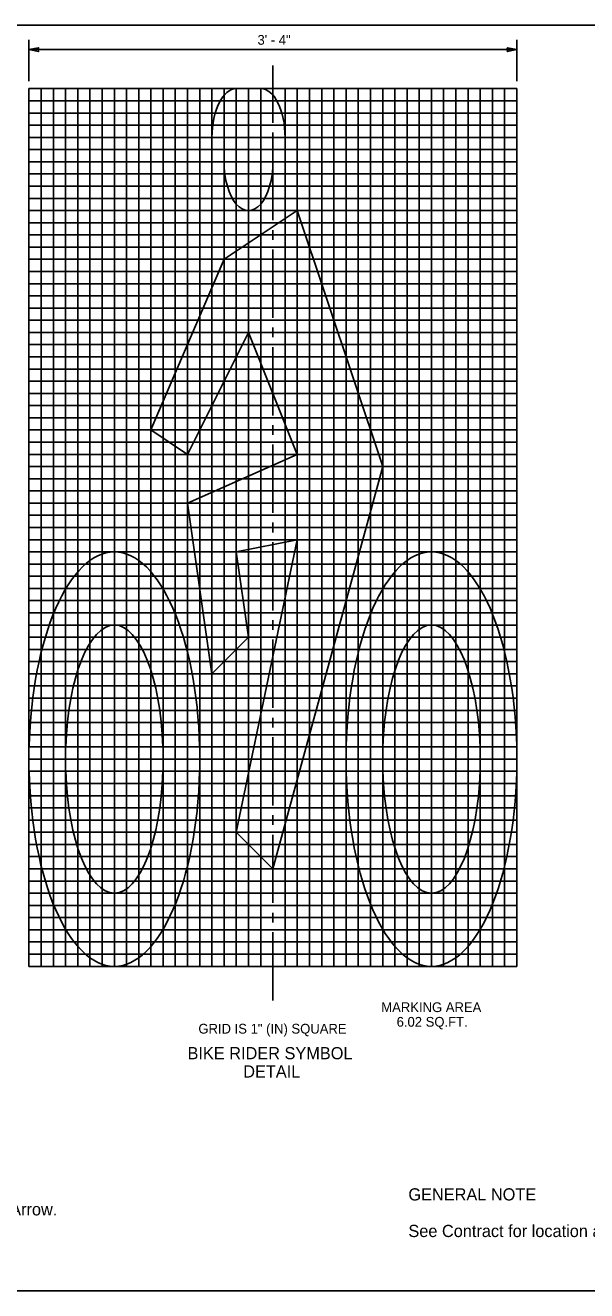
# Model space of a CAD drawing. Extents: x 99862 to 104211, y 98939 to 102076.
# Drawn here: x 101116 to 102036, y 100000 to 102076 of the extents above; entities that cross this region are included whole.
import ezdxf

# ---------------------------------------------------------------- set-up
doc = ezdxf.new("R2010")
doc.units = 0
for name, color, linetype in [('Level 1', 7, 'Continuous'), ('Level 15', 7, 'Continuous'), ('Level 2', 7, 'Continuous'), ('Level 20', 7, 'Continuous'), ('Level 7', 7, 'Continuous')]:
    doc.layers.add(name, color=color, linetype=linetype)

msp = doc.modelspace()

# ---------------------------------------------------------------- linework, layer by layer
at = {"layer": 'Level 1'}
msp.add_lwpolyline([(99862, 99999.5), (103151, 99999.5), (103151, 102075.5), (99862, 102075.5)], close=True, dxfattribs=at)
at = {"layer": 'Level 15'}
for p, q in [((101121.8, 101983.6), (101121.8, 102051.6)), ((101121.8, 102035.6), (101921.8, 102035.6)), ((101921.8, 101983.6), (101921.8, 102051.6)), ((101521.8, 102009.6), (101521.8, 101915.6)), ((101521.8, 101899.6), (101521.8, 101883.6)), ((101521.8, 101867.6), (101521.8, 101755.6)), ((101521.8, 101739.6), (101521.8, 101723.6)), ((101521.8, 101707.6), (101521.8, 101595.6)), ((101521.8, 101579.6), (101521.8, 101563.6)), ((101521.8, 101547.6), (101521.8, 101435.6)), ((101521.8, 101419.6), (101521.8, 101403.6)), ((101521.8, 101387.6), (101521.8, 101275.6)), ((101521.8, 101259.6), (101521.8, 101243.6)), ((101521.8, 101227.6), (101521.8, 101115.6)), ((101521.8, 101099.6), (101521.8, 101083.6)), ((101521.8, 101067.6), (101521.8, 100955.6)), ((101521.8, 100939.6), (101521.8, 100923.6)), ((101521.8, 100907.6), (101521.8, 100795.6)), ((101521.8, 100779.6), (101521.8, 100763.6)), ((101521.8, 100747.6), (101521.8, 100635.6)), ((101521.8, 100619.6), (101521.8, 100603.6)), ((101521.8, 100587.6), (101521.8, 100475.6))]:
    msp.add_line(p, q, dxfattribs=at)
for points in [[(101121.8, 102035.6), (101137.5, 102032.5), (101136.8, 102035.6), (101137.5, 102038.7)], [(101921.8, 102035.6), (101906.1, 102032.5), (101906.8, 102035.6), (101906.1, 102038.7)]]:
    msp.add_lwpolyline(points, close=True, dxfattribs=at)
at = {"layer": 'Level 2'}
for p, q in [((101121.8, 101971.6), (101521.8, 101971.6)), ((101121.8, 100531.6), (101121.8, 101971.6)), ((101141.8, 101251.6), (101141.8, 101971.6)), ((101161.8, 101251.6), (101161.8, 101971.6)), ((101181.8, 101251.6), (101181.8, 101971.6)), ((101201.8, 101251.6), (101201.8, 101971.6)), ((101221.8, 101251.6), (101221.8, 101971.6)), ((101241.8, 100531.6), (101241.8, 101971.6)), ((101261.8, 101251.6), (101261.8, 101971.6)), ((101281.8, 101251.6), (101281.8, 101971.6)), ((101301.8, 101251.6), (101301.8, 101971.6)), ((101321.8, 101251.6), (101321.8, 101971.6)), ((101341.8, 101251.6), (101341.8, 101971.6)), ((101361.8, 100531.6), (101361.8, 101971.6)), ((101381.8, 101251.6), (101381.8, 101971.6)), ((101401.8, 101251.6), (101401.8, 101971.6)), ((101421.8, 101251.6), (101421.8, 101971.6)), ((101441.8, 101251.6), (101441.8, 101971.6)), ((101461.8, 101251.6), (101461.8, 101971.6)), ((101481.8, 100531.6), (101481.8, 101971.6)), ((101501.8, 101251.6), (101501.8, 101971.6)), ((101521.8, 101971.6), (101921.8, 101971.6)), ((101541.8, 101251.6), (101541.8, 101971.6)), ((101561.8, 101251.6), (101561.8, 101971.6)), ((101581.8, 101251.6), (101581.8, 101971.6)), ((101601.8, 100531.6), (101601.8, 101971.6)), ((101621.8, 101251.6), (101621.8, 101971.6)), ((101641.8, 101251.6), (101641.8, 101971.6)), ((101661.8, 101251.6), (101661.8, 101971.6)), ((101681.8, 101251.6), (101681.8, 101971.6)), ((101701.8, 101251.6), (101701.8, 101971.6)), ((101721.8, 100531.6), (101721.8, 101971.6)), ((101741.8, 101251.6), (101741.8, 101971.6)), ((101761.8, 101251.6), (101761.8, 101971.6)), ((101781.8, 101251.6), (101781.8, 101971.6)), ((101801.8, 101251.6), (101801.8, 101971.6)), ((101821.8, 101251.6), (101821.8, 101971.6)), ((101841.8, 100531.6), (101841.8, 101971.6)), ((101861.8, 101251.6), (101861.8, 101971.6)), ((101881.8, 101251.6), (101881.8, 101971.6)), ((101901.8, 101251.6), (101901.8, 101971.6)), ((101921.8, 101251.6), (101921.8, 101971.6)), ((101121.8, 101951.6), (101521.8, 101951.6)), ((101521.8, 101951.6), (101921.8, 101951.6)), ((101121.8, 101931.6), (101521.8, 101931.6)), ((101121.8, 101911.6), (101521.8, 101911.6)), ((101521.8, 101931.6), (101921.8, 101931.6)), ((101521.8, 101911.6), (101921.8, 101911.6)), ((101121.8, 101891.6), (101521.8, 101891.6)), ((101521.8, 101891.6), (101921.8, 101891.6)), ((101121.8, 101871.6), (101521.8, 101871.6)), ((101521.8, 101871.6), (101921.8, 101871.6)), ((101121.8, 101851.6), (101921.8, 101851.6)), ((101121.8, 101831.6), (101521.8, 101831.6)), ((101521.8, 101831.6), (101921.8, 101831.6)), ((101121.8, 101811.6), (101521.8, 101811.6)), ((101521.8, 101811.6), (101921.8, 101811.6)), ((101121.8, 101791.6), (101521.8, 101791.6)), ((101521.8, 101791.6), (101921.8, 101791.6)), ((101121.8, 101771.6), (101521.8, 101771.6)), ((101521.8, 101771.6), (101921.8, 101771.6)), ((101121.8, 101751.6), (101521.8, 101751.6)), ((101521.8, 101751.6), (101921.8, 101751.6)), ((101121.8, 101731.6), (101921.8, 101731.6)), ((101121.8, 101711.6), (101521.8, 101711.6)), ((101521.8, 101711.6), (101921.8, 101711.6)), ((101121.8, 101691.6), (101521.8, 101691.6)), ((101521.8, 101691.6), (101921.8, 101691.6)), ((101121.8, 101671.6), (101521.8, 101671.6)), ((101521.8, 101671.6), (101921.8, 101671.6)), ((101121.8, 101651.6), (101521.8, 101651.6)), ((101521.8, 101651.6), (101921.8, 101651.6)), ((101121.8, 101631.6), (101521.8, 101631.6)), ((101521.8, 101631.6), (101921.8, 101631.6)), ((101121.8, 101611.6), (101921.8, 101611.6)), ((101121.8, 101591.6), (101521.8, 101591.6)), ((101521.8, 101591.6), (101921.8, 101591.6)), ((101121.8, 101571.6), (101521.8, 101571.6)), ((101521.8, 101571.6), (101921.8, 101571.6)), ((101121.8, 101551.6), (101521.8, 101551.6)), ((101521.8, 101551.6), (101921.8, 101551.6)), ((101121.8, 101531.6), (101521.8, 101531.6)), ((101521.8, 101531.6), (101921.8, 101531.6)), ((101121.8, 101511.6), (101521.8, 101511.6)), ((101521.8, 101511.6), (101921.8, 101511.6)), ((101121.8, 101491.6), (101921.8, 101491.6)), ((101121.8, 101471.6), (101521.8, 101471.6)), ((101521.8, 101471.6), (101921.8, 101471.6)), ((101121.8, 101451.6), (101521.8, 101451.6)), ((101521.8, 101451.6), (101921.8, 101451.6)), ((101121.8, 101431.6), (101521.8, 101431.6)), ((101521.8, 101431.6), (101921.8, 101431.6)), ((101121.8, 101411.6), (101521.8, 101411.6)), ((101521.8, 101411.6), (101921.8, 101411.6)), ((101121.8, 101391.6), (101521.8, 101391.6)), ((101121.8, 101371.6), (101921.8, 101371.6)), ((101521.8, 101391.6), (101921.8, 101391.6)), ((101121.8, 101351.6), (101521.8, 101351.6)), ((101521.8, 101351.6), (101921.8, 101351.6)), ((101121.8, 101331.6), (101521.8, 101331.6)), ((101521.8, 101331.6), (101921.8, 101331.6)), ((101121.8, 101311.6), (101521.8, 101311.6)), ((101521.8, 101311.6), (101921.8, 101311.6)), ((101121.8, 101291.6), (101521.8, 101291.6)), ((101521.8, 101291.6), (101921.8, 101291.6)), ((101121.8, 101271.6), (101521.8, 101271.6)), ((101521.8, 101271.6), (101921.8, 101271.6)), ((101121.8, 101251.6), (101921.8, 101251.6)), ((101141.8, 100531.6), (101141.8, 101251.6)), ((101161.8, 100531.6), (101161.8, 101251.6)), ((101181.8, 100531.6), (101181.8, 101251.6)), ((101201.8, 100531.6), (101201.8, 101251.6)), ((101221.8, 100531.6), (101221.8, 101251.6)), ((101261.8, 100531.6), (101261.8, 101251.6)), ((101281.8, 100531.6), (101281.8, 101251.6)), ((101301.8, 100531.6), (101301.8, 101251.6)), ((101321.8, 100531.6), (101321.8, 101251.6)), ((101341.8, 100531.6), (101341.8, 101251.6)), ((101381.8, 100531.6), (101381.8, 101251.6)), ((101401.8, 100531.6), (101401.8, 101251.6)), ((101421.8, 100531.6), (101421.8, 101251.6)), ((101441.8, 100531.6), (101441.8, 101251.6)), ((101461.8, 100531.6), (101461.8, 101251.6)), ((101501.8, 100531.6), (101501.8, 101251.6)), ((101541.8, 100531.6), (101541.8, 101251.6)), ((101561.8, 100531.6), (101561.8, 101251.6)), ((101581.8, 100531.6), (101581.8, 101251.6)), ((101621.8, 100531.6), (101621.8, 101251.6)), ((101641.8, 100531.6), (101641.8, 101251.6)), ((101661.8, 100531.6), (101661.8, 101251.6)), ((101681.8, 100531.6), (101681.8, 101251.6)), ((101701.8, 100531.6), (101701.8, 101251.6)), ((101741.8, 100531.6), (101741.8, 101251.6)), ((101761.8, 100531.6), (101761.8, 101251.6)), ((101781.8, 100531.6), (101781.8, 101251.6)), ((101801.8, 100531.6), (101801.8, 101251.6)), ((101821.8, 100531.6), (101821.8, 101251.6)), ((101861.8, 100531.6), (101861.8, 101251.6)), ((101881.8, 100531.6), (101881.8, 101251.6)), ((101901.8, 100531.6), (101901.8, 101251.6)), ((101921.8, 100531.6), (101921.8, 101251.6)), ((101121.8, 101231.6), (101521.8, 101231.6)), ((101521.8, 101231.6), (101921.8, 101231.6)), ((101121.8, 101211.6), (101521.8, 101211.6)), ((101521.8, 101211.6), (101921.8, 101211.6)), ((101121.8, 101191.6), (101521.8, 101191.6)), ((101521.8, 101191.6), (101921.8, 101191.6)), ((101121.8, 101171.6), (101521.8, 101171.6)), ((101521.8, 101171.6), (101921.8, 101171.6)), ((101121.8, 101151.6), (101521.8, 101151.6)), ((101521.8, 101151.6), (101921.8, 101151.6)), ((101121.8, 101131.6), (101921.8, 101131.6)), ((101121.8, 101111.6), (101521.8, 101111.6)), ((101521.8, 101111.6), (101921.8, 101111.6)), ((101121.8, 101091.6), (101521.8, 101091.6)), ((101521.8, 101091.6), (101921.8, 101091.6)), ((101121.8, 101071.6), (101521.8, 101071.6)), ((101521.8, 101071.6), (101921.8, 101071.6)), ((101121.8, 101051.6), (101521.8, 101051.6)), ((101521.8, 101051.6), (101921.8, 101051.6)), ((101121.8, 101031.6), (101521.8, 101031.6)), ((101521.8, 101031.6), (101921.8, 101031.6)), ((101121.8, 101011.6), (101921.8, 101011.6)), ((101121.8, 100991.6), (101521.8, 100991.6)), ((101521.8, 100991.6), (101921.8, 100991.6)), ((101121.8, 100971.6), (101521.8, 100971.6)), ((101521.8, 100971.6), (101921.8, 100971.6)), ((101121.8, 100951.6), (101521.8, 100951.6)), ((101521.8, 100951.6), (101921.8, 100951.6)), ((101121.8, 100931.6), (101521.8, 100931.6)), ((101521.8, 100931.6), (101921.8, 100931.6)), ((101121.8, 100911.6), (101521.8, 100911.6)), ((101521.8, 100911.6), (101921.8, 100911.6)), ((101121.8, 100891.6), (101921.8, 100891.6)), ((101121.8, 100871.6), (101521.8, 100871.6)), ((101521.8, 100871.6), (101921.8, 100871.6)), ((101121.8, 100851.6), (101521.8, 100851.6)), ((101121.8, 100831.6), (101521.8, 100831.6)), ((101521.8, 100851.6), (101921.8, 100851.6)), ((101521.8, 100831.6), (101921.8, 100831.6)), ((101121.8, 100811.6), (101521.8, 100811.6)), ((101521.8, 100811.6), (101921.8, 100811.6)), ((101121.8, 100791.6), (101521.8, 100791.6)), ((101521.8, 100791.6), (101921.8, 100791.6)), ((101121.8, 100771.6), (101921.8, 100771.6)), ((101121.8, 100751.6), (101521.8, 100751.6)), ((101521.8, 100751.6), (101921.8, 100751.6)), ((101121.8, 100731.6), (101521.8, 100731.6)), ((101521.8, 100731.6), (101921.8, 100731.6)), ((101121.8, 100711.6), (101521.8, 100711.6)), ((101521.8, 100711.6), (101921.8, 100711.6)), ((101121.8, 100691.6), (101521.8, 100691.6)), ((101521.8, 100691.6), (101921.8, 100691.6)), ((101121.8, 100671.6), (101521.8, 100671.6)), ((101521.8, 100671.6), (101921.8, 100671.6)), ((101121.8, 100651.6), (101921.8, 100651.6)), ((101121.8, 100631.6), (101521.8, 100631.6)), ((101521.8, 100631.6), (101921.8, 100631.6)), ((101121.8, 100611.6), (101521.8, 100611.6)), ((101521.8, 100611.6), (101921.8, 100611.6)), ((101121.8, 100591.6), (101521.8, 100591.6)), ((101521.8, 100591.6), (101921.8, 100591.6)), ((101121.8, 100571.6), (101521.8, 100571.6)), ((101521.8, 100571.6), (101921.8, 100571.6)), ((101121.8, 100551.6), (101521.8, 100551.6)), ((101521.8, 100551.6), (101921.8, 100551.6)), ((101121.8, 100531.6), (101521.8, 100531.6)), ((101521.8, 100531.6), (101921.8, 100531.6))]:
    msp.add_line(p, q, dxfattribs=at)
at = {"layer": 'Level 7'}
for points in [[(101501.8, 101971.6), (101461.8, 101971.6)], [(101421.8, 101891.6), (101441.8, 101891.6), (101441.8, 101851.6)], [(101521.8, 101851.6), (101521.8, 101891.6), (101541.8, 101891.6)], [(101122.1, 100891.6), (101182.1, 100891.6)], [(101341.5, 100891.6), (101401.6, 100891.6)], [(101642.1, 100891.6), (101702.1, 100891.6)], [(101861.5, 100891.6), (101921.6, 100891.6)], [(101182.1, 100851.6), (101122.1, 100851.6)], [(101401.6, 100851.6), (101341.5, 100851.6)], [(101702.1, 100851.6), (101642.1, 100851.6)], [(101921.6, 100851.6), (101861.5, 100851.6)]]:
    msp.add_lwpolyline(points, dxfattribs=at)
msp.add_lwpolyline([(101461.8, 101211.6), (101561.8, 101231.6), (101461.8, 100751.6), (101521.8, 100691.6), (101701.8, 101351.6), (101561.8, 101771.6), (101441.8, 101691.6), (101321.8, 101411.6), (101381.8, 101371.6), (101481.8, 101571.6), (101561.8, 101371.6), (101381.8, 101291.6), (101421.8, 101011.6), (101481.8, 101071.6)], close=True, dxfattribs=at)
for centre, major_axis, ratio, start_param, end_param in [((101461.8, 101891.6), (0, 80), 0.5, 0, 1.570796), ((101501.8, 101891.6), (0, 80), 0.5, 4.712389, 6.283185), ((101481.8, 101851.6), (0, -80), 0.5, 4.712389, 7.853982), ((101261.8, 100871.6), (0, 340), 0.411765, 4.771246, 7.795124), ((101781.8, 100871.6), (0, 340), 0.411765, 4.771246, 7.795124), ((101261.8, 100871.6), (0, 220), 0.363636, 4.803424, 7.762947), ((101781.8, 100871.6), (0, 220), 0.363636, 4.803424, 7.762947), ((101261.8, 100871.6), (0, 340), 0.411765, 1.629654, 4.653531), ((101261.8, 100871.6), (0, 220), 0.363636, 1.661831, 4.621354), ((101781.8, 100871.6), (0, 340), 0.411765, 1.629654, 4.653531), ((101781.8, 100871.6), (0, 220), 0.363636, 1.661831, 4.621354)]:
    msp.add_ellipse(centre, major_axis=major_axis, ratio=ratio, start_param=start_param, end_param=end_param, dxfattribs=at)

# ---------------------------------------------------------------- texts
at = {"layer": 'Level 20'}
for s, height, p in [('3\' - 4"', 16, (101496.5, 102043.6)), ('MARKING AREA', 16, (101699.5, 100456.6)), ('GRID IS 1" (IN) SQUARE', 16, (101399.6, 100421.3)), ('6.02 SQ.FT.', 16, (101724.7, 100432.6)), ('GENERAL NOTE', 20, (101744, 100147.5)), ("2' (ft) x 6' (ft) White Bike Lane Arrow.", 20, (100733, 100123)), ('See Contract for location and material requirements.', 20, (101744, 100087.5))]:
    msp.add_text(s, height=height, dxfattribs=at).set_placement(p)
for s, p in [('BIKE RIDER SYMBOL', (101381.8, 100379.2)), ('DETAIL', (101473.1, 100349.2))]:
    msp.add_text(s, height=20, rotation=360, dxfattribs=at).set_placement(p)

doc.saveas('drawing.dxf')
